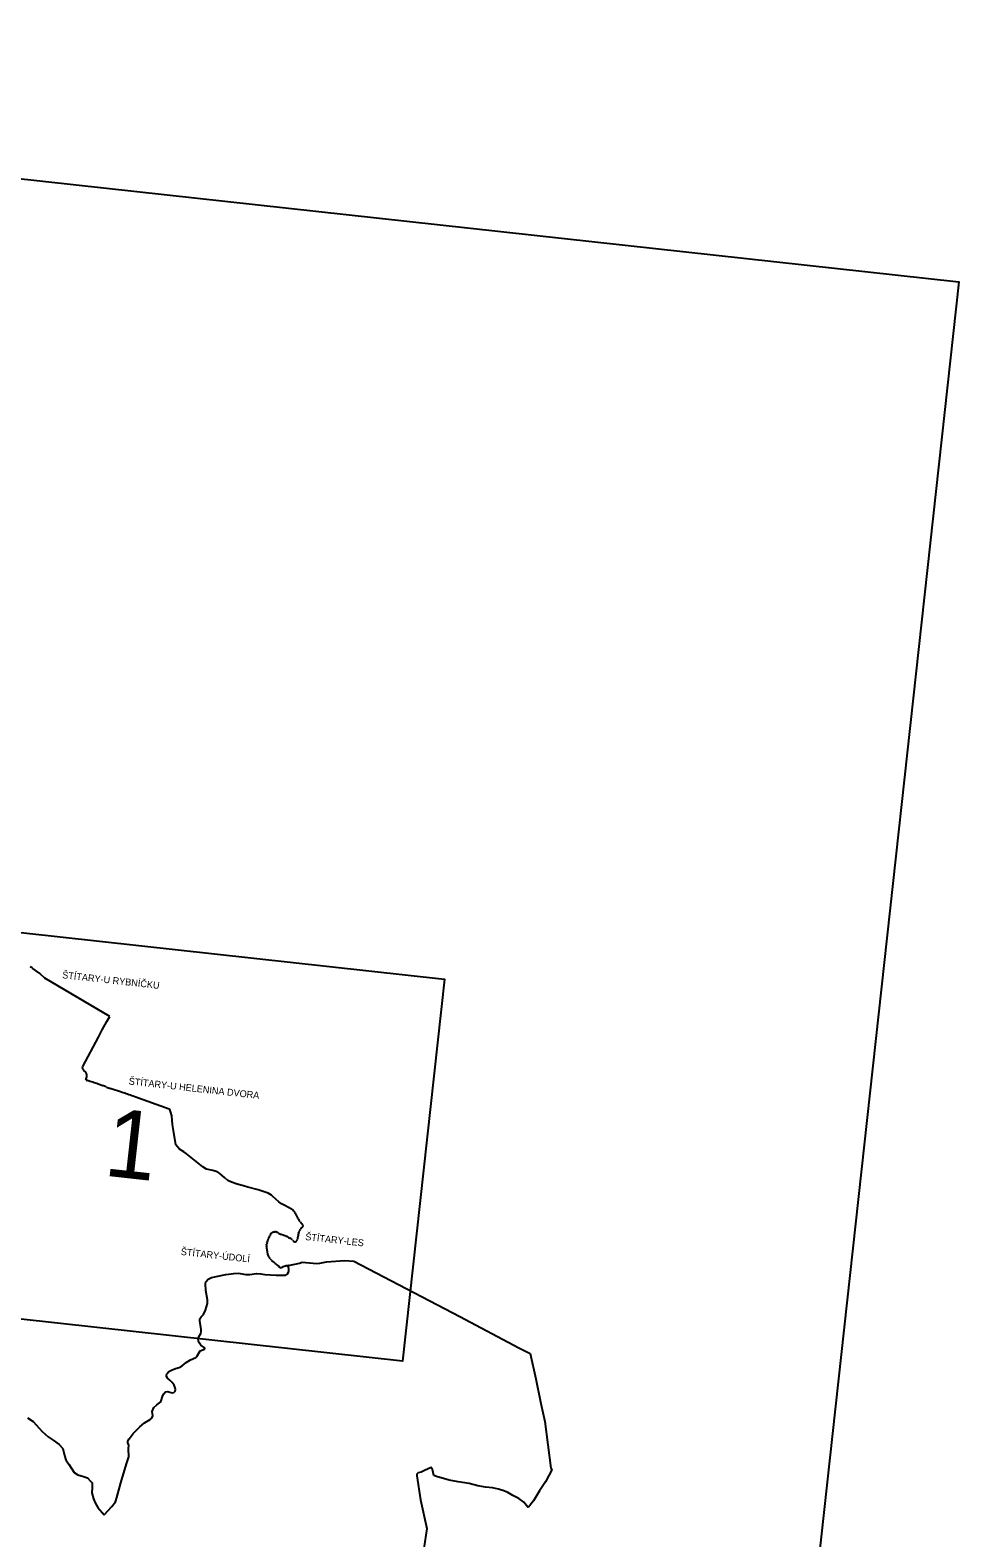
# Model space of a CAD drawing. Extents: x -678204 to -526855, y -1228851 to -1110393.
# Drawn here: x -660037 to -651868, y -1187099 to -1173846 of the extents above; entities that cross this region are included whole.
import ezdxf

# ---------------------------------------------------------------- set-up
doc = ezdxf.new("R2010")
doc.units = 0
for name, color, linetype in [('00_n_cyklo popisy detaily', 7, 'Continuous'), ('00_n_cyklo prujezdne rekreacni hlavni', 7, 'Continuous'), ('00_n_cyklo prujezdne rekreacni vedlejsi', 7, 'Continuous'), ('00_n_cyklo studie rekreacni vedlejsi', 7, 'Continuous'), ('00_n_cyklo trasovani rekreacni hlavni', 7, 'Continuous'), ('00_n_cyklo trasovani rekreacni vedlejsi', 7, 'Continuous'), ('_HELP', 7, 'Continuous'), ('_HELP BIG', 7, 'Continuous')]:
    doc.layers.add(name, color=color, linetype=linetype)

msp = doc.modelspace()

# ---------------------------------------------------------------- linework, layer by layer
at = {"layer": '00_n_cyklo prujezdne rekreacni hlavni'}
for points in [[(-659386, -1186896), (-659319, -1186822), (-659287, -1186781), (-659274, -1186745), (-659239, -1186615), (-659189, -1186448), (-659168, -1186387), (-659171, -1186313), (-659170, -1186285), (-659177, -1186264), (-659178, -1186249), (-659165, -1186228), (-659131, -1186181), (-659072, -1186123), (-659031, -1186088), (-658981, -1186058), (-658967, -1186046), (-658959, -1186027), (-658964, -1185988), (-658950, -1185954), (-658922, -1185929), (-658888, -1185902), (-658872, -1185857), (-658864, -1185836), (-658845, -1185815), (-658825, -1185812), (-658807, -1185819), (-658788, -1185824), (-658774, -1185820), (-658762, -1185810), (-658758, -1185796), (-658761, -1185780), (-658770, -1185757), (-658788, -1185734), (-658809, -1185713), (-658829, -1185695), (-658837, -1185681), (-658837, -1185668), (-658834, -1185656), (-658818, -1185637), (-658793, -1185624), (-658759, -1185610), (-658726, -1185600), (-658701, -1185587), (-658664, -1185558), (-658625, -1185534), (-658580, -1185513), (-658570, -1185504), (-658542, -1185455), (-658504, -1185439), (-658501, -1185430), (-658506, -1185424), (-658535, -1185404), (-658548, -1185387), (-658556, -1185370), (-658558, -1185347), (-658550, -1185325), (-658536, -1185303), (-658532, -1185286), (-658532, -1185267), (-658545, -1185192), (-658544, -1185173), (-658532, -1185156), (-658512, -1185135), (-658494, -1185097), (-658478, -1185040), (-658478, -1185005), (-658492, -1184925), (-658493, -1184867), (-658490, -1184847), (-658470, -1184825), (-658443, -1184811), (-658315, -1184784), (-658244, -1184774), (-658207, -1184773), (-658190, -1184775), (-658141, -1184784), (-658105, -1184784), (-658046, -1184776), (-658009, -1184778), (-657972, -1184783), (-657872, -1184791), (-657817, -1184790), (-657794, -1184789), (-657774, -1184778), (-657763, -1184762), (-657760, -1184748), (-657765, -1184706), (-657668, -1184685), (-657643, -1184675), (-657514, -1184686), (-657490, -1184684), (-657429, -1184673), (-657269, -1184662), (-657191, -1184667), (-656992, -1184770), (-656257, -1185153), (-655739, -1185427), (-655639, -1185478), (-655588, -1185700), (-655545, -1185918), (-655509, -1186076), (-655457, -1186487)], [(-660060, -1186043), (-660011, -1186077), (-659930, -1186163), (-659879, -1186212), (-659834, -1186241), (-659782, -1186278), (-659748, -1186314), (-659734, -1186375), (-659724, -1186414), (-659698, -1186447), (-659695, -1186451), (-659648, -1186525), (-659618, -1186544), (-659567, -1186558), (-659532, -1186572), (-659505, -1186599), (-659492, -1186614), (-659490, -1186660), (-659493, -1186704), (-659479, -1186755), (-659466, -1186790), (-659440, -1186832), (-659386, -1186896)], [(-656510, -1186479), (-656568, -1186507), (-656596, -1186522), (-656623, -1186528), (-656636, -1186538), (-656636, -1186553), (-656603, -1186763), (-656549, -1187017), (-656582, -1187251)], [(-655633, -1186802), (-655651, -1186826), (-655658, -1186830), (-655694, -1186785), (-655738, -1186754), (-655790, -1186727), (-655836, -1186699), (-655871, -1186685), (-655916, -1186670), (-655970, -1186658), (-656033, -1186654), (-656098, -1186642), (-656174, -1186621), (-656272, -1186607), (-656350, -1186592), (-656464, -1186559), (-656485, -1186550), (-656499, -1186497), (-656511, -1186478)], [(-655457, -1186487), (-655448, -1186501), (-655476, -1186550), (-655505, -1186606), (-655556, -1186685), (-655610, -1186773), (-655633, -1186802)]]:
    msp.add_lwpolyline(points, dxfattribs=at)
at = {"layer": '00_n_cyklo prujezdne rekreacni vedlejsi'}
for points in [[(-659546, -1183070), (-659547, -1183069), (-659543, -1183064), (-659541, -1183056), (-659538, -1183045), (-659538, -1183031), (-659540, -1183018), (-659546, -1183006), (-659564, -1182991), (-659572, -1182979), (-659575, -1182967), (-659572, -1182956), (-659436, -1182698), (-659403, -1182633), (-659362, -1182559), (-659337, -1182515)], [(-657770, -1184191), (-657791, -1184179), (-657825, -1184162), (-657850, -1184144), (-657902, -1184099), (-657915, -1184085), (-657942, -1184070), (-658030, -1184039), (-658122, -1184017), (-658161, -1184005), (-658216, -1183990), (-658267, -1183972), (-658297, -1183958), (-658323, -1183935), (-658367, -1183896), (-658386, -1183883), (-658400, -1183877), (-658431, -1183871), (-658486, -1183859), (-658519, -1183836), (-658664, -1183721), (-658684, -1183706), (-658723, -1183683), (-658754, -1183645), (-658776, -1183519), (-658784, -1183465), (-658788, -1183427), (-658790, -1183389), (-658798, -1183359), (-658805, -1183343), (-658808, -1183333), (-658813, -1183329)]]:
    msp.add_lwpolyline(points, dxfattribs=at)
at = {"layer": '00_n_cyklo studie rekreacni vedlejsi'}
for p, q in [((-659961, -1182131), (-660013, -1182094)), ((-659911, -1182176), (-659943, -1182147)), ((-659337, -1182515), (-659908, -1182179)), ((-659545, -1183071), (-659546, -1183070)), ((-659397, -1183125), (-659438, -1183110)), ((-659367, -1183137), (-659371, -1183135)), ((-659323, -1183152), (-659329, -1183150)), ((-659218, -1183187), (-659252, -1183175)), ((-658813, -1183329), (-659117, -1183221)), ((-657758, -1184197), (-657770, -1184191)), ((-657742, -1184206), (-657749, -1184202)), ((-657726, -1184218), (-657730, -1184215)), ((-657714, -1184230), (-657717, -1184227)), ((-657703, -1184245), (-657705, -1184242)), ((-657693, -1184265), (-657695, -1184260)), ((-657686, -1184281), (-657689, -1184273)), ((-657682, -1184291), (-657682, -1184290)), ((-657664, -1184392), (-657658, -1184384)), ((-657640, -1184346), (-657647, -1184339)), ((-657638, -1184350), (-657639, -1184349)), ((-657637, -1184361), (-657637, -1184361)), ((-657636, -1184355), (-657636, -1184355)), ((-657957, -1184524), (-657957, -1184518)), ((-657954, -1184503), (-657952, -1184496)), ((-657948, -1184486), (-657944, -1184477)), ((-657938, -1184464), (-657936, -1184459)), ((-657929, -1184444), (-657928, -1184442)), ((-657923, -1184432), (-657920, -1184426)), ((-657916, -1184420), (-657912, -1184418)), ((-657907, -1184415), (-657905, -1184414)), ((-657896, -1184411), (-657888, -1184409)), ((-657880, -1184409), (-657875, -1184409)), ((-657869, -1184411), (-657867, -1184411)), ((-657862, -1184414), (-657858, -1184416)), ((-657851, -1184419), (-657840, -1184425)), ((-657789, -1184446), (-657785, -1184448)), ((-657742, -1184471), (-657736, -1184475)), ((-657729, -1184481), (-657722, -1184488)), ((-657715, -1184493), (-657713, -1184495)), ((-657709, -1184496), (-657709, -1184496)), ((-657705, -1184496), (-657703, -1184496)), ((-657700, -1184495), (-657700, -1184495)), ((-657693, -1184489), (-657693, -1184489)), ((-657690, -1184485), (-657686, -1184478)), ((-657683, -1184470), (-657682, -1184466)), ((-657681, -1184461), (-657680, -1184447)), ((-657679, -1184439), (-657678, -1184431)), ((-657677, -1184424), (-657674, -1184415)), ((-657671, -1184405), (-657668, -1184399)), ((-657958, -1184540), (-657958, -1184537)), ((-657956, -1184558), (-657957, -1184557)), ((-657939, -1184625), (-657941, -1184619)), ((-657937, -1184630), (-657937, -1184630)), ((-657926, -1184646), (-657931, -1184640)), ((-657915, -1184659), (-657921, -1184653)), ((-657904, -1184667), (-657905, -1184667)), ((-657894, -1184675), (-657898, -1184671)), ((-657884, -1184684), (-657885, -1184683)), ((-657866, -1184699), (-657874, -1184692)), ((-657849, -1184711), (-657855, -1184707)), ((-657843, -1184721), (-657845, -1184716)), ((-657835, -1184724), (-657837, -1184724)), ((-657816, -1184718), (-657821, -1184720)), ((-657794, -1184710), (-657811, -1184716)), ((-657780, -1184708), (-657789, -1184709)), ((-657765, -1184705), (-657769, -1184706))]:
    msp.add_line(p, q, dxfattribs=at)
for points in [[(-659484, -1183094), (-659509, -1183086), (-659536, -1183077)], [(-657663, -1184320), (-657667, -1184315), (-657674, -1184305)], [(-657652, -1184377), (-657642, -1184367), (-657639, -1184365)], [(-657829, -1184430), (-657814, -1184436), (-657804, -1184440)], [(-657773, -1184454), (-657765, -1184458), (-657752, -1184465)], [(-657943, -1184613), (-657945, -1184605), (-657950, -1184584), (-657953, -1184574)]]:
    msp.add_lwpolyline(points, dxfattribs=at)
for centre, radius, start, end in [((-660131, -1182255), 200, 53.8381, 61.9425), ((-660079, -1182293), 200, 46.8298, 53.8381), ((-659898, -1182162), 20, 226.8298, 239.4819), ((-659530, -1183058), 20, 220.5079, 252.5113), ((-659785, -1184048), 1000, 69.69, 72.5242), ((-659744, -1184062), 1000, 68.0476, 69.69), ((-659180, -1182673), 500, 248.0476, 252.6449), ((-660218, -1186015), 3000, 71.2118, 72.6449), ((-662438, -1192654), 10000, 70.6049, 71.2118), ((-657802, -1184287), 100, 58.2043, 64.1446), ((-657795, -1184291), 100, 49.4254, 58.2043), ((-657791, -1184294), 100, 42.234, 49.4254), ((-657788, -1184297), 100, 33.191, 42.234), ((-657787, -1184300), 100, 23.7862, 33.191), ((-657876, -1184345), 200, 21.1556, 23.7862), ((-657593, -1184245), 100, 201.1556, 206.5102), ((-657592, -1184247), 100, 206.5102, 215.4186), ((-657500, -1184203), 200, 215.7447, 222.8937), ((-657617, -1184413), 50, 133.0745, 144.9005), ((-657651, -1184356), 15, 31.3222, 42.8937), ((-657646, -1184358), 10, 313.9046, 343.4866), ((-657646, -1184356), 10, 3.8663, 31.3222), ((-657651, -1184356), 15, 343.4866, 3.8663), ((-657857, -1184530), 100, 164.2868, 172.9808), ((-657855, -1184523), 100, 158.1582, 164.2868), ((-657852, -1184514), 100, 149.9662, 158.1582), ((-658022, -1184409), 100, 329.9662, 339.3893), ((-657834, -1184477), 100, 153.1698, 159.3893), ((-657907, -1184432), 15, 126.621, 153.1698), ((-657897, -1184438), 25, 113.5942, 126.621), ((-657885, -1184460), 50, 102.9027, 113.5942), ((-657883, -1184434), 25, 83.5696, 102.9027), ((-657878, -1184434), 25, 69.9169, 83.5696), ((-657885, -1184458), 50, 62.7333, 69.9169), ((-658087, -1184860), 500, 61.9, 62.7333), ((-657793, -1184337), 100, 241.9, 248.6082), ((-657915, -1184719), 300, 65.2821, 68.3701), ((-657995, -1184902), 500, 63.6587, 65.2821), ((-657798, -1184554), 100, 55.9694, 62.3587), ((-657764, -1184516), 50, 45.4467, 55.9694), ((-657687, -1184452), 50, 225.4467, 234.7854), ((-657707, -1184486), 10, 234.7854, 259.2238), ((-657707, -1184487), 10, 259.2238, 281.1609), ((-657706, -1184481), 15, 281.1609, 292.2715), ((-657706, -1184481), 15, 292.2715, 326.4994), ((-657776, -1184434), 100, 326.4994, 329.5307), ((-657712, -1184462), 30, 329.5307, 345.3104), ((-657711, -1184459), 30, 345.3104, 355.3801), ((-657480, -1184463), 200, 173.076, 175.3801), ((-657628, -1184437), 50, 165.7807, 173.076), ((-657626, -1184427), 50, 153.8478, 165.7807), ((-657623, -1184421), 50, 144.9005, 153.8478), ((-657858, -1184537), 100, 172.9808, 179.9552), ((-657858, -1184540), 100, 179.9552, 189.8454), ((-657759, -1184524), 200, 189.8454, 194.2618), ((-657846, -1184587), 100, 194.816, 198.363), ((-657892, -1184609), 50, 198.363, 204.7616), ((-657892, -1184609), 50, 204.7616, 218.5086), ((-657848, -1184584), 100, 218.5086, 223.2551), ((-657882, -1184628), 45, 223.2551, 239.5683), ((-657927, -1184706), 45, 49.9329, 59.5683), ((-657990, -1184790), 150, 45.4264, 49.9329), ((-657813, -1184613), 100, 225.4264, 232.3838), ((-657744, -1184540), 200, 232.3838, 236.5061), ((-657854, -1184719), 10, 18.7619, 56.5061), ((-657838, -1184719), 5, 198.7619, 281.7433), ((-657855, -1184626), 100, 281.7433, 290.3098), ((-659552, -1180029), 5000, 290.3098, 290.3805), ((-657787, -1184729), 20, 95.6065, 110.3805), ((-657790, -1184608), 100, 275.6065, 281.8131)]:
    msp.add_arc(centre, radius, start, end, dxfattribs=at)
at = {"layer": '00_n_cyklo trasovani rekreacni hlavni'}
for points in [[(-659386, -1186896), (-659319, -1186822), (-659287, -1186781), (-659274, -1186745), (-659239, -1186615), (-659189, -1186448), (-659168, -1186387), (-659171, -1186313), (-659170, -1186285), (-659177, -1186264), (-659178, -1186249), (-659165, -1186228), (-659131, -1186181), (-659072, -1186123), (-659031, -1186088), (-658981, -1186058), (-658967, -1186046), (-658959, -1186027), (-658964, -1185988), (-658950, -1185954), (-658922, -1185929), (-658888, -1185902), (-658872, -1185857), (-658864, -1185836), (-658845, -1185815), (-658825, -1185812), (-658807, -1185819), (-658788, -1185824), (-658774, -1185820), (-658762, -1185810), (-658758, -1185796), (-658761, -1185780), (-658770, -1185757), (-658788, -1185734), (-658809, -1185713), (-658829, -1185695), (-658837, -1185681), (-658837, -1185668), (-658834, -1185656), (-658818, -1185637), (-658793, -1185624), (-658759, -1185610), (-658726, -1185600), (-658701, -1185587), (-658664, -1185558), (-658625, -1185534), (-658580, -1185513), (-658570, -1185504), (-658542, -1185455), (-658504, -1185439), (-658501, -1185430), (-658506, -1185424), (-658535, -1185404), (-658548, -1185387), (-658556, -1185370), (-658558, -1185347), (-658550, -1185325), (-658536, -1185303), (-658532, -1185286), (-658532, -1185267), (-658545, -1185192), (-658544, -1185173), (-658532, -1185156), (-658512, -1185135), (-658494, -1185097), (-658478, -1185040), (-658478, -1185005), (-658492, -1184925), (-658493, -1184867), (-658490, -1184847), (-658470, -1184825), (-658443, -1184811), (-658315, -1184784), (-658244, -1184774), (-658207, -1184773), (-658190, -1184775), (-658141, -1184784), (-658105, -1184784), (-658046, -1184776), (-658009, -1184778), (-657972, -1184783), (-657872, -1184791), (-657817, -1184790), (-657794, -1184789), (-657774, -1184778), (-657763, -1184762), (-657760, -1184748), (-657765, -1184706), (-657668, -1184685), (-657643, -1184675), (-657514, -1184686), (-657490, -1184684), (-657429, -1184673), (-657269, -1184662), (-657191, -1184667), (-656992, -1184770), (-656257, -1185153), (-655739, -1185427), (-655639, -1185478), (-655588, -1185700), (-655545, -1185918), (-655509, -1186076), (-655457, -1186487)], [(-660060, -1186043), (-660011, -1186077), (-659930, -1186163), (-659879, -1186212), (-659834, -1186241), (-659782, -1186278), (-659748, -1186314), (-659734, -1186375), (-659724, -1186414), (-659698, -1186447), (-659695, -1186451), (-659648, -1186525), (-659618, -1186544), (-659567, -1186558), (-659532, -1186572), (-659505, -1186599), (-659492, -1186614), (-659490, -1186660), (-659493, -1186704), (-659479, -1186755), (-659466, -1186790), (-659440, -1186832), (-659386, -1186896)], [(-656510, -1186479), (-656568, -1186507), (-656596, -1186522), (-656623, -1186528), (-656636, -1186538), (-656636, -1186553), (-656603, -1186763), (-656549, -1187017), (-656582, -1187251)], [(-655633, -1186802), (-655651, -1186826), (-655658, -1186830), (-655694, -1186785), (-655738, -1186754), (-655790, -1186727), (-655836, -1186699), (-655871, -1186685), (-655916, -1186670), (-655970, -1186658), (-656033, -1186654), (-656098, -1186642), (-656174, -1186621), (-656272, -1186607), (-656350, -1186592), (-656464, -1186559), (-656485, -1186550), (-656499, -1186497), (-656511, -1186478)], [(-655457, -1186487), (-655448, -1186501), (-655476, -1186550), (-655505, -1186606), (-655556, -1186685), (-655610, -1186773), (-655633, -1186802)]]:
    msp.add_lwpolyline(points, dxfattribs=at)
at = {"layer": '00_n_cyklo trasovani rekreacni vedlejsi'}
for p, q in [((-659961, -1182131), (-660013, -1182094)), ((-659911, -1182176), (-659943, -1182147)), ((-659337, -1182515), (-659908, -1182179)), ((-659545, -1183071), (-659546, -1183070)), ((-659397, -1183125), (-659438, -1183110)), ((-659367, -1183137), (-659371, -1183135)), ((-659323, -1183152), (-659329, -1183150)), ((-659218, -1183187), (-659252, -1183175)), ((-658813, -1183329), (-659117, -1183221)), ((-657758, -1184197), (-657770, -1184191)), ((-657742, -1184206), (-657749, -1184202)), ((-657726, -1184218), (-657730, -1184215)), ((-657714, -1184230), (-657717, -1184227)), ((-657703, -1184245), (-657705, -1184242)), ((-657693, -1184265), (-657695, -1184260)), ((-657686, -1184281), (-657689, -1184273)), ((-657682, -1184291), (-657682, -1184290)), ((-657664, -1184392), (-657658, -1184384)), ((-657640, -1184346), (-657647, -1184339)), ((-657638, -1184350), (-657639, -1184349)), ((-657637, -1184361), (-657637, -1184361)), ((-657636, -1184355), (-657636, -1184355)), ((-657957, -1184524), (-657957, -1184518)), ((-657954, -1184503), (-657952, -1184496)), ((-657948, -1184486), (-657944, -1184477)), ((-657938, -1184464), (-657936, -1184459)), ((-657929, -1184444), (-657928, -1184442)), ((-657923, -1184432), (-657920, -1184426)), ((-657916, -1184420), (-657912, -1184418)), ((-657907, -1184415), (-657905, -1184414)), ((-657896, -1184411), (-657888, -1184409)), ((-657880, -1184409), (-657875, -1184409)), ((-657869, -1184411), (-657867, -1184411)), ((-657862, -1184414), (-657858, -1184416)), ((-657851, -1184419), (-657840, -1184425)), ((-657789, -1184446), (-657785, -1184448)), ((-657742, -1184471), (-657736, -1184475)), ((-657729, -1184481), (-657722, -1184488)), ((-657715, -1184493), (-657713, -1184495)), ((-657709, -1184496), (-657709, -1184496)), ((-657705, -1184496), (-657703, -1184496)), ((-657700, -1184495), (-657700, -1184495)), ((-657693, -1184489), (-657693, -1184489)), ((-657690, -1184485), (-657686, -1184478)), ((-657683, -1184470), (-657682, -1184466)), ((-657681, -1184461), (-657680, -1184447)), ((-657679, -1184439), (-657678, -1184431)), ((-657677, -1184424), (-657674, -1184415)), ((-657671, -1184405), (-657668, -1184399)), ((-657958, -1184540), (-657958, -1184537)), ((-657956, -1184558), (-657957, -1184557)), ((-657939, -1184625), (-657941, -1184619)), ((-657937, -1184630), (-657937, -1184630)), ((-657926, -1184646), (-657931, -1184640)), ((-657915, -1184659), (-657921, -1184653)), ((-657904, -1184667), (-657905, -1184667)), ((-657894, -1184675), (-657898, -1184671)), ((-657884, -1184684), (-657885, -1184683)), ((-657866, -1184699), (-657874, -1184692)), ((-657849, -1184711), (-657855, -1184707)), ((-657843, -1184721), (-657845, -1184716)), ((-657835, -1184724), (-657837, -1184724)), ((-657816, -1184718), (-657821, -1184720)), ((-657794, -1184710), (-657811, -1184716)), ((-657780, -1184708), (-657789, -1184709)), ((-657765, -1184705), (-657769, -1184706))]:
    msp.add_line(p, q, dxfattribs=at)
for points in [[(-659546, -1183070), (-659547, -1183069), (-659543, -1183064), (-659541, -1183056), (-659538, -1183045), (-659538, -1183031), (-659540, -1183018), (-659546, -1183006), (-659564, -1182991), (-659572, -1182979), (-659575, -1182967), (-659572, -1182956), (-659436, -1182698), (-659403, -1182633), (-659362, -1182559), (-659337, -1182515)], [(-659484, -1183094), (-659509, -1183086), (-659536, -1183077)], [(-657770, -1184191), (-657791, -1184179), (-657825, -1184162), (-657850, -1184144), (-657902, -1184099), (-657915, -1184085), (-657942, -1184070), (-658030, -1184039), (-658122, -1184017), (-658161, -1184005), (-658216, -1183990), (-658267, -1183972), (-658297, -1183958), (-658323, -1183935), (-658367, -1183896), (-658386, -1183883), (-658400, -1183877), (-658431, -1183871), (-658486, -1183859), (-658519, -1183836), (-658664, -1183721), (-658684, -1183706), (-658723, -1183683), (-658754, -1183645), (-658776, -1183519), (-658784, -1183465), (-658788, -1183427), (-658790, -1183389), (-658798, -1183359), (-658805, -1183343), (-658808, -1183333), (-658813, -1183329)], [(-657663, -1184320), (-657667, -1184315), (-657674, -1184305)], [(-657652, -1184377), (-657642, -1184367), (-657639, -1184365)], [(-657829, -1184430), (-657814, -1184436), (-657804, -1184440)], [(-657773, -1184454), (-657765, -1184458), (-657752, -1184465)], [(-657943, -1184613), (-657945, -1184605), (-657950, -1184584), (-657953, -1184574)]]:
    msp.add_lwpolyline(points, dxfattribs=at)
for centre, radius, start, end in [((-660131, -1182255), 200, 53.8381, 61.9425), ((-660079, -1182293), 200, 46.8298, 53.8381), ((-659898, -1182162), 20, 226.8298, 239.4819), ((-659530, -1183058), 20, 220.5079, 252.5113), ((-659785, -1184048), 1000, 69.69, 72.5242), ((-659744, -1184062), 1000, 68.0476, 69.69), ((-659180, -1182673), 500, 248.0476, 252.6449), ((-660218, -1186015), 3000, 71.2118, 72.6449), ((-662438, -1192654), 10000, 70.6049, 71.2118), ((-657802, -1184287), 100, 58.2043, 64.1446), ((-657795, -1184291), 100, 49.4254, 58.2043), ((-657791, -1184294), 100, 42.234, 49.4254), ((-657788, -1184297), 100, 33.191, 42.234), ((-657787, -1184300), 100, 23.7862, 33.191), ((-657876, -1184345), 200, 21.1556, 23.7862), ((-657593, -1184245), 100, 201.1556, 206.5102), ((-657592, -1184247), 100, 206.5102, 215.4186), ((-657500, -1184203), 200, 215.7447, 222.8937), ((-657617, -1184413), 50, 133.0745, 144.9005), ((-657651, -1184356), 15, 31.3222, 42.8937), ((-657646, -1184358), 10, 313.9046, 343.4866), ((-657646, -1184356), 10, 3.8663, 31.3222), ((-657651, -1184356), 15, 343.4866, 3.8663), ((-657857, -1184530), 100, 164.2868, 172.9808), ((-657855, -1184523), 100, 158.1582, 164.2868), ((-657852, -1184514), 100, 149.9662, 158.1582), ((-658022, -1184409), 100, 329.9662, 339.3893), ((-657834, -1184477), 100, 153.1698, 159.3893), ((-657907, -1184432), 15, 126.621, 153.1698), ((-657897, -1184438), 25, 113.5942, 126.621), ((-657885, -1184460), 50, 102.9027, 113.5942), ((-657883, -1184434), 25, 83.5696, 102.9027), ((-657878, -1184434), 25, 69.9169, 83.5696), ((-657885, -1184458), 50, 62.7333, 69.9169), ((-658087, -1184860), 500, 61.9, 62.7333), ((-657793, -1184337), 100, 241.9, 248.6082), ((-657915, -1184719), 300, 65.2821, 68.3701), ((-657995, -1184902), 500, 63.6587, 65.2821), ((-657798, -1184554), 100, 55.9694, 62.3587), ((-657764, -1184516), 50, 45.4467, 55.9694), ((-657687, -1184452), 50, 225.4467, 234.7854), ((-657707, -1184486), 10, 234.7854, 259.2238), ((-657707, -1184487), 10, 259.2238, 281.1609), ((-657706, -1184481), 15, 281.1609, 292.2715), ((-657706, -1184481), 15, 292.2715, 326.4994), ((-657776, -1184434), 100, 326.4994, 329.5307), ((-657712, -1184462), 30, 329.5307, 345.3104), ((-657711, -1184459), 30, 345.3104, 355.3801), ((-657480, -1184463), 200, 173.076, 175.3801), ((-657628, -1184437), 50, 165.7807, 173.076), ((-657626, -1184427), 50, 153.8478, 165.7807), ((-657623, -1184421), 50, 144.9005, 153.8478), ((-657858, -1184537), 100, 172.9808, 179.9552), ((-657858, -1184540), 100, 179.9552, 189.8454), ((-657759, -1184524), 200, 189.8454, 194.2618), ((-657846, -1184587), 100, 194.816, 198.363), ((-657892, -1184609), 50, 198.363, 204.7616), ((-657892, -1184609), 50, 204.7616, 218.5086), ((-657848, -1184584), 100, 218.5086, 223.2551), ((-657882, -1184628), 45, 223.2551, 239.5683), ((-657927, -1184706), 45, 49.9329, 59.5683), ((-657990, -1184790), 150, 45.4264, 49.9329), ((-657813, -1184613), 100, 225.4264, 232.3838), ((-657744, -1184540), 200, 232.3838, 236.5061), ((-657854, -1184719), 10, 18.7619, 56.5061), ((-657838, -1184719), 5, 198.7619, 281.7433), ((-657855, -1184626), 100, 281.7433, 290.3098), ((-659552, -1180029), 5000, 290.3098, 290.3805), ((-657787, -1184729), 20, 95.6065, 110.3805), ((-657790, -1184608), 100, 275.6065, 281.8131)]:
    msp.add_arc(centre, radius, start, end, dxfattribs=at)
at = {"layer": '_HELP'}
msp.add_lwpolyline([(-661107, -1181670), (-656392, -1182187), (-656761, -1185545), (-661476, -1185027)], close=True, dxfattribs=at)
at = {"layer": '_HELP BIG'}
msp.add_lwpolyline([(-675119, -1202133), (-672013, -1173846), (-651868, -1176058), (-654974, -1204345)], close=True, dxfattribs=at)

# ---------------------------------------------------------------- texts
at = {"layer": '00_n_cyklo popisy detaily'}
for s, p in [('ŠTÍTARY-U RYBNÍČKU', (-659757, -1182179)), ('ŠTÍTARY-U HELENINA DVORA', (-659172, -1183113)), ('ŠTÍTARY-LES', (-657619, -1184480)), ('ŠTÍTARY-ÚDOLÍ', (-658714, -1184611))]:
    msp.add_text(s, height=60, rotation=353.6836, dxfattribs=at).set_placement(p)
at = {"layer": '_HELP'}
msp.add_text('1', height=600, rotation=353.6836, dxfattribs=at).set_placement((-659398, -1183913))

doc.saveas('drawing.dxf')
